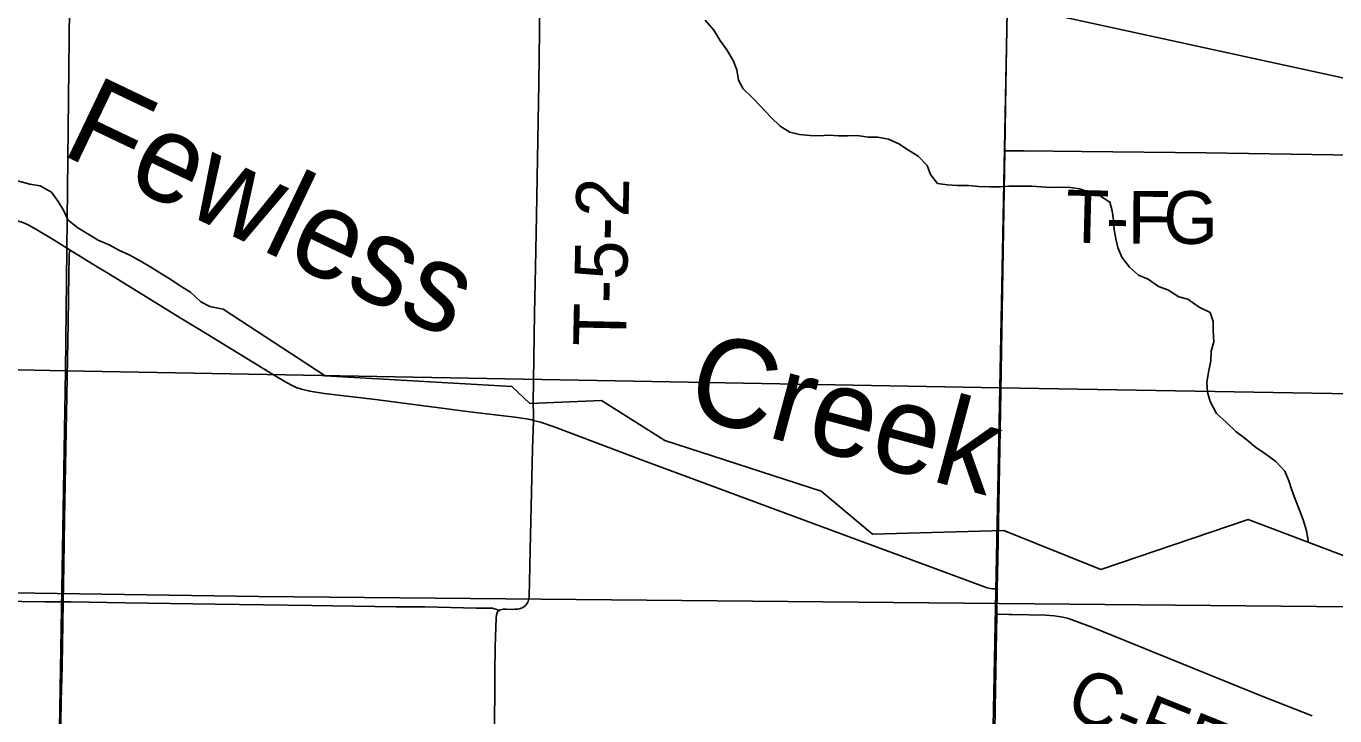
# Model space of a CAD drawing. Extents: x 0 to 42, y 0 to 22.
# Drawn here: x 7.178 to 8.588, y 16.093 to 16.836 of the extents above; entities that cross this region are included whole.
import ezdxf

# ---------------------------------------------------------------- set-up
doc = ezdxf.new("R2010")
doc.units = 0
for name, color, linetype in [('Default', 7, 'Continuous'), ('GM_X_County_Road', 7, 'Continuous'), ('GM_X_County_Road_Text', 7, 'Continuous'), ('GM_X_Minor_River', 7, 'Continuous'), ('GM_X_Minor_River_Text', 7, 'Continuous'), ('GM_X_Rail_Line', 7, 'Continuous'), ('GM_X_Section', 7, 'Continuous'), ('GM_X_Township_Road', 7, 'Continuous'), ('GM_X_Township_Road_Text', 7, 'Continuous'), ('SH_Text', 7, 'Continuous')]:
    doc.layers.add(name, color=color, linetype=linetype)

msp = doc.modelspace()

# ---------------------------------------------------------------- linework, layer by layer
at = {"layer": 'Default'}
for points in [[(8.9, 16.4352), (8.9, 17.4474), (8.2465, 17.4593), (8.2267, 16.4466)], [(8.9, 15.4308), (8.9, 16.4352), (8.2267, 16.4466), (8.207, 15.4431)]]:
    msp.add_lwpolyline(points, close=True, dxfattribs=at)
at = {"layer": 'GM_X_County_Road'}
msp.add_line((8.2236, 16.2028), (8.2241, 16.23), dxfattribs=at)
for points in [[(7.7246, 16.4117), (7.7245, 16.4183), (7.7242, 16.4307), (7.7257, 16.527), (7.7266, 16.5766), (7.7277, 16.6321), (7.7302, 16.775), (7.7324, 16.9428), (7.7342, 17.064), (7.7356, 17.1447), (7.7376, 17.2877), (7.7387, 17.3529), (7.74, 17.4337), (7.7406, 17.4706)], [(8.2323, 16.7021), (8.2335, 16.7724), (8.2363, 16.9341), (8.2371, 16.9745), (8.2376, 17.0024), (8.2384, 17.0366), (8.2389, 17.0646), (8.2397, 17.1019), (8.2411, 17.1765), (8.2431, 17.2697), (8.2446, 17.3444), (8.2456, 17.391), (8.246, 17.419), (8.2464, 17.4469), (8.2466, 17.4576)], [(8.2241, 16.23), (8.2246, 16.2626), (8.2274, 16.4212), (8.2293, 16.53), (8.2323, 16.7021)], [(6.4244, 16.6564), (6.4392, 16.6551), (6.4453, 16.6544), (6.4608, 16.6536), (6.5632, 16.6504), (6.6315, 16.6479), (6.6688, 16.6464), (6.8613, 16.6398), (6.9792, 16.636), (7.0506, 16.6333), (7.1469, 16.63), (7.1563, 16.6293), (7.1625, 16.6283), (7.1686, 16.6268), (7.1745, 16.6248), (7.1803, 16.6222), (7.1885, 16.6177), (7.2072, 16.6065), (7.2256, 16.595)], [(7.2256, 16.595), (7.2547, 16.577), (7.2679, 16.5692), (7.3439, 16.5222), (7.373, 16.5045), (7.4446, 16.4608), (7.4579, 16.4528), (7.466, 16.4484), (7.4688, 16.4472), (7.4746, 16.4453), (7.4835, 16.4431), (7.4989, 16.4406), (7.5544, 16.4342), (7.6559, 16.421), (7.7046, 16.415), (7.7168, 16.4133), (7.723, 16.4122), (7.7246, 16.4117)], [(7.6877, 16.2067), (7.6887, 16.2075), (7.692, 16.2082), (7.6952, 16.2083), (7.7015, 16.208), (7.7046, 16.2081), (7.7076, 16.2084), (7.7105, 16.2091), (7.7132, 16.2102), (7.7156, 16.2118), (7.7174, 16.214), (7.7187, 16.2165), (7.7194, 16.2193), (7.7197, 16.2223), (7.7201, 16.2378), (7.721, 16.272), (7.7226, 16.3497), (7.7233, 16.3808), (7.7246, 16.4117)], [(7.7246, 16.4117), (7.7321, 16.4097), (7.7468, 16.4046), (7.8427, 16.3686), (7.901, 16.3469), (7.9968, 16.3115), (8.0812, 16.2802), (8.1482, 16.2553), (8.2065, 16.2337), (8.2131, 16.2312), (8.2167, 16.2304), (8.2191, 16.23), (8.2221, 16.23), (8.2241, 16.23)], [(7.673, 15.7041), (7.6756, 15.775), (7.6767, 15.8153), (7.6781, 15.8432), (7.6782, 15.8534), (7.6787, 15.8687), (7.679, 15.8839), (7.68, 15.9068), (7.6803, 15.9317), (7.6808, 15.9781), (7.6815, 16.0154), (7.6824, 16.0683), (7.683, 16.1398), (7.6832, 16.1678), (7.6842, 16.1989), (7.6847, 16.2021), (7.6859, 16.2053), (7.6877, 16.2067)], [(8.2084, 15.4481), (8.2093, 15.4919), (8.2105, 15.5354), (8.2115, 15.5883), (8.2134, 15.6721), (8.2152, 15.7591), (8.2183, 15.902), (8.2195, 15.9673), (8.2207, 16.0295), (8.2218, 16.101), (8.223, 16.1632), (8.2236, 16.2028)], [(8.2236, 16.2028), (8.2255, 16.2028), (8.2367, 16.2024), (8.2397, 16.2024), (8.276, 16.2016), (8.2854, 16.201), (8.2947, 16.1996), (8.3008, 16.1981), (8.3067, 16.1962), (8.3271, 16.1885), (8.373, 16.1698), (8.5083, 16.115), (8.5632, 16.0932)]]:
    msp.add_lwpolyline(points, dxfattribs=at)
at = {"layer": 'GM_X_Minor_River'}
for points in [[(8.5595, 16.2802), (8.5573, 16.2926), (8.5538, 16.3033), (8.5502, 16.3132), (8.5451, 16.3266), (8.5415, 16.3366), (8.5383, 16.3465), (8.534, 16.3569), (8.524, 16.3673), (8.5135, 16.3751), (8.5023, 16.3829), (8.4911, 16.3923), (8.481, 16.3997), (8.4706, 16.4098), (8.4602, 16.4191), (8.4533, 16.4321), (8.4504, 16.4421), (8.4499, 16.4523), (8.4516, 16.4637), (8.4541, 16.4758), (8.4544, 16.4864), (8.4572, 16.4962), (8.4567, 16.5088), (8.4565, 16.5183), (8.4533, 16.5278), (8.4417, 16.5337), (8.4293, 16.5424), (8.4195, 16.5448), (8.4079, 16.5523), (8.3978, 16.5559), (8.3866, 16.5637), (8.3764, 16.5681), (8.3664, 16.5766), (8.3583, 16.5874), (8.3539, 16.5978), (8.3518, 16.6073), (8.3501, 16.6168), (8.3492, 16.6275), (8.3479, 16.6374), (8.3454, 16.6469), (8.3342, 16.654), (8.3237, 16.6576), (8.3127, 16.6613), (8.3029, 16.6626), (8.2927, 16.6628), (8.2813, 16.6627), (8.2715, 16.6632), (8.2613, 16.6642), (8.2484, 16.6641), (8.2367, 16.6639), (8.2272, 16.6634), (8.2162, 16.6632), (8.2041, 16.6638), (8.1935, 16.6648), (8.181, 16.6647), (8.1704, 16.6653), (8.1598, 16.667), (8.152, 16.6766), (8.1485, 16.6862), (8.1388, 16.6963), (8.1283, 16.7029), (8.1179, 16.7096), (8.107, 16.7148), (8.0953, 16.7169), (8.085, 16.7167), (8.0733, 16.7185), (8.0627, 16.7183), (8.0529, 16.7181), (8.043, 16.7191), (8.0324, 16.7182), (8.0226, 16.7187), (8.0112, 16.7197), (8.0007, 16.7222), (7.9902, 16.7285), (7.9801, 16.7382), (7.9701, 16.749), (7.9601, 16.7595), (7.9504, 16.7688), (7.9453, 16.7784), (7.9437, 16.7894), (7.9397, 16.7994), (7.9327, 16.8109), (7.9253, 16.8213), (7.9187, 16.8321), (7.9095, 16.8429)], [(7.376, 16.5343), (7.3663, 16.5395), (7.3551, 16.5499), (7.3439, 16.5566), (7.3338, 16.5633), (7.3237, 16.5696), (7.3125, 16.5766), (7.3027, 16.5825), (7.2896, 16.5896), (7.278, 16.5952), (7.2682, 16.6003), (7.2555, 16.6059), (7.2457, 16.6121), (7.2337, 16.6192), (7.2229, 16.6278), (7.2186, 16.6374), (7.2127, 16.6474), (7.2053, 16.6574), (7.1933, 16.6644), (7.182, 16.6662), (7.1688, 16.6699)], [(8.6631, 16.2411), (8.4943, 16.3049), (8.3357, 16.2511), (8.2312, 16.2931), (8.0898, 16.2891), (8.0345, 16.3354), (7.866, 16.3901), (7.7979, 16.4332), (7.7206, 16.4298), (7.7012, 16.4481), (7.5003, 16.4597), (7.3904, 16.5314), (7.376, 16.5343)]]:
    msp.add_lwpolyline(points, dxfattribs=at)
at = {"layer": 'GM_X_Rail_Line'}
msp.add_lwpolyline([(4.4607, 16.2608), (4.6655, 16.258), (5.6831, 16.252), (6.101, 16.2418), (7.4287, 16.222), (8.568, 16.211), (8.9, 16.2074)], dxfattribs=at)
at = {"layer": 'GM_X_Section'}
for points in [[(6.2427, 17.4846), (7.2316, 17.475), (7.2205, 16.4649), (6.2249, 16.4863), (6.224, 16.494)], [(7.2316, 17.475), (8.2465, 17.4593), (8.2267, 16.4466), (7.2205, 16.4649)], [(6.2249, 16.4863), (7.2205, 16.4649), (7.2034, 15.459), (6.2056, 15.4786)], [(7.2205, 16.4649), (8.2267, 16.4466), (8.207, 15.4431), (7.2034, 15.459)]]:
    msp.add_lwpolyline(points, close=True, dxfattribs=at)
at = {"layer": 'GM_X_Township_Road'}
for points in [[(7.7246, 16.4117), (7.7245, 16.4183), (7.7242, 16.4307), (7.7257, 16.527), (7.7266, 16.5766), (7.7277, 16.6321), (7.7302, 16.775), (7.7324, 16.9428), (7.7342, 17.064), (7.7356, 17.1447), (7.7376, 17.2877), (7.7387, 17.3529), (7.74, 17.4337), (7.7406, 17.4706)], [(8.2323, 16.7021), (8.2436, 16.702), (8.253, 16.702), (8.3152, 16.7014), (8.4491, 16.6999), (8.586, 16.6979), (8.7293, 16.6966), (8.7417, 16.6959), (8.754, 16.6946), (8.7694, 16.6922), (8.9, 16.6683)], [(7.2178, 16.216), (7.2185, 16.2556), (7.2193, 16.3053), (7.2222, 16.4576), (7.2234, 16.5167), (7.2241, 16.5695), (7.2242, 16.5887), (7.2243, 16.5909), (7.2249, 16.5928), (7.2256, 16.595)], [(6.5691, 16.2242), (6.5951, 16.2245), (6.6884, 16.2234), (6.7567, 16.2227), (6.794, 16.2221), (6.9184, 16.2209), (7.0303, 16.2191), (7.1235, 16.2173), (7.1982, 16.216), (7.2178, 16.216)], [(7.2026, 15.4619), (7.2028, 15.4707), (7.2034, 15.4889), (7.2034, 15.4983), (7.2039, 15.5168), (7.2052, 15.6006), (7.206, 15.6285), (7.2075, 15.6907), (7.2088, 15.7334), (7.2085, 15.7458), (7.2088, 15.7582), (7.2095, 15.7955), (7.2115, 15.8794), (7.2125, 15.9292), (7.2139, 16.0131), (7.215, 16.0628), (7.2156, 16.1095), (7.2167, 16.1467), (7.2178, 16.216)], [(7.2178, 16.216), (7.2261, 16.216), (7.2852, 16.2151), (7.3815, 16.2135), (7.4859, 16.2122), (7.5763, 16.2108), (7.6074, 16.2106), (7.6633, 16.2095), (7.6759, 16.2095), (7.6771, 16.2095), (7.6789, 16.2094), (7.6802, 16.2092), (7.6816, 16.2088), (7.6839, 16.2081), (7.6858, 16.2074), (7.6877, 16.2067)]]:
    msp.add_lwpolyline(points, dxfattribs=at)
at = {"layer": 'SH_Text'}
msp.add_lwpolyline([(9.439, 16.8599), (5.3926, 17.4787), (9.439, 16.5971)], close=True, dxfattribs=at)

# ---------------------------------------------------------------- texts
at = {"layer": 'GM_X_County_Road_Text'}
msp.add_text('C-EF', height=0.05682, rotation=338.0803, dxfattribs=at).set_placement((8.2951, 16.095))
at = {"layer": 'GM_X_Minor_River_Text'}
for s, height, rotation, p in [('Fewless', 0.09477, 334.4532, (7.2137, 16.6993)), ('Creek', 0.09476, 345.0239, (7.8858, 16.4179))]:
    msp.add_text(s, height=height, rotation=rotation, dxfattribs=at).set_placement(p)
at = {"layer": 'GM_X_Township_Road_Text'}
for s, height, rotation, p in [('T-5-2', 0.05682, 88.8225, (7.824, 16.491)), ('T', 0.0568, 358.5599, (8.2974, 16.6035)), ('F', 0.0568, 359.6157, (8.3643, 16.6022)), ('G', 0.0568, 359.6583, (8.4027, 16.602)), ('-', 0.0568, 359.4811, (8.3408, 16.6024))]:
    msp.add_text(s, height=height, rotation=rotation, dxfattribs=at).set_placement(p)

doc.saveas('drawing.dxf')
